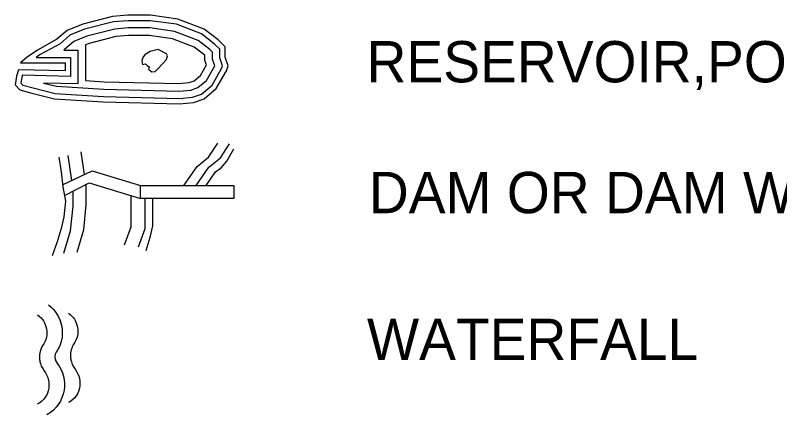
# Model space of a CAD drawing. Extents: x 5197761 to 5514561, y 1890130 to 2080942.
# Drawn here: x 5487538 to 5496796, y 1996107 to 2000941 of the extents above; entities that cross this region are included whole.
import ezdxf

# ---------------------------------------------------------------- set-up
doc = ezdxf.new("R2010")
doc.units = 0
for name, color, linetype in [('Exist Hydrographic Buffer Line', 7, 'Continuous'), ('Exist Hydrographic Island Shore', 7, 'Continuous'), ('Exist Hydrographic Lake Dam', 7, 'Continuous'), ('Exist Hydrographic Lake Shore', 7, 'Continuous'), ('Exist Hydrographic Lake Shore Label', 7, 'Continuous'), ('Exist Hydrographic River Shore', 7, 'Continuous'), ('Exist Hydrographic Waterfall CELL', 7, 'Continuous'), ('Exist Hydrographic Waterfall Label', 7, 'Continuous')]:
    doc.layers.add(name, color=color, linetype=linetype)

msp = doc.modelspace()

# ---------------------------------------------------------------- linework, layer by layer
at = {"layer": 'Exist Hydrographic Buffer Line'}
for points in [[(5487624.3, 2000216.7), (5487617, 2000192.5), (5487606.6, 2000119.7), (5487627.4, 2000096), (5487753.2, 2000062.9), (5488022.7, 1999995.5), (5488605, 1999957.7), (5489526.2, 1999934.9), (5489682.7, 1999949.1), (5489794, 1999988.4), (5489921.6, 2000095.8), (5490035.7, 2000295.5), (5490048.5, 2000329.6), (5490014.4, 2000424.9), (5490014.4, 2000531.7), (5489952.2, 2000593.9), (5489794.7, 2000715.6), (5489489.1, 2000832.1), (5489171.7, 2000876.4), (5488903.3, 2000876.4), (5488727.7, 2000861.7), (5488377.3, 2000772.3), (5488200.2, 2000701.4), (5488080.7, 2000596.9), (5487840.1, 2000464.9), (5487792.7, 2000432.4), (5488207.8, 2000432.4), (5488207.8, 2000200.9)], [(5487880.9, 2000121.7), (5488036.3, 2000082.8), (5488608.9, 2000045.7), (5489523.3, 2000023), (5489663.8, 2000035.8), (5489749.6, 2000066), (5489852.9, 2000153), (5489954.5, 2000330.9), (5489926.4, 2000409.7), (5489926.4, 2000495.3), (5489893.9, 2000527.7), (5489751.2, 2000638), (5489467, 2000746.3), (5489165.6, 2000788.3), (5488907, 2000788.3), (5488742.4, 2000774.6), (5488404.7, 2000688.4), (5488246.9, 2000625.3), (5488131.5, 2000524.3), (5488124.3, 2000520.4), (5488295.9, 2000520.4), (5488295.9, 2000110.5)], [(5489703.2, 2000147.1), (5489781.2, 2000212.8), (5489853.8, 2000339.8), (5489834.5, 2000393.8), (5489834.5, 2000457.2), (5489833.1, 2000458.6), (5489705.8, 2000557), (5489444.1, 2000656.7), (5489159.2, 2000696.5), (5488910.8, 2000696.5), (5488757.6, 2000683.7), (5488433.2, 2000600.9), (5488387.7, 2000582.7), (5488387.7, 2000152.1), (5488613, 2000137.5), (5489520.2, 2000115), (5489644.1, 2000126.2)]]:
    msp.add_lwpolyline(points, close=True, dxfattribs=at)
for points in [[(5489580.5, 1998881.3), (5489739.5, 1999112.5), (5489880.1, 1999223), (5489990.6, 1999393.8)], [(5489728.5, 1998881.3), (5489882.2, 1999104.8), (5490022.8, 1999215.3), (5490133.3, 1999386)], [(5488376.2, 1999014.6), (5488336.4, 1999286.9)], [(5488222.5, 1998941.6), (5488178.1, 1999245.4)], [(5488286.2, 1998075.7), (5488366.5, 1998346.9), (5488396.6, 1998648.2), (5488396.6, 1998893.7)], [(5488127.8, 1998060.1), (5488208.2, 1998331.3), (5488238.3, 1998632.7), (5488238.3, 1998813.4)], [(5488860.7, 1998161.2), (5488941.1, 1998382.2), (5488941.1, 1998573.1), (5488941.1, 1998757.9)], [(5489029.4, 1998140.4), (5489109.7, 1998361.4), (5489109.7, 1998552.3), (5489109.7, 1998723.1)]]:
    msp.add_lwpolyline(points, dxfattribs=at)
at = {"layer": 'Exist Hydrographic Island Shore'}
msp.add_lwpolyline([(5489268, 2000526.1), (5489170.4, 2000505.1), (5489113, 2000468.7), (5489086.2, 2000438.1), (5489069, 2000394.1), (5489080.5, 2000344.3), (5489114.9, 2000355.8), (5489134.1, 2000332.9), (5489162.8, 2000313.7), (5489153.2, 2000288.8), (5489191.5, 2000256.3), (5489231.7, 2000262), (5489264.2, 2000294.6), (5489321.6, 2000352), (5489367.6, 2000405.6), (5489382.9, 2000451.5), (5489367.6, 2000474.5)], close=True, dxfattribs=at)
at = {"layer": 'Exist Hydrographic Lake Dam'}
for points in [[(5488111.5, 1998888.9), (5488470.9, 1999059.6), (5489056, 1998881.3)], [(5488132.6, 1998759.8), (5488432.5, 1998911.9), (5489056, 1998723.1)]]:
    msp.add_lwpolyline(points, dxfattribs=at)
msp.add_lwpolyline([(5489056, 1998881.3), (5490183.5, 1998881.3), (5490183.5, 1998723.1), (5489056, 1998723.1)], close=True, dxfattribs=at)
at = {"layer": 'Exist Hydrographic Lake Shore'}
msp.add_lwpolyline([(5488012.6, 1999931), (5488602.1, 1999892.7), (5489528.3, 1999869.7), (5489696.7, 1999885), (5489826.9, 1999931), (5489972.3, 2000053.4), (5490094.8, 2000267.8), (5490117.8, 2000329), (5490079.5, 2000436.2), (5490079.5, 2000497.4), (5490079.5, 2000558.7), (5489995.3, 2000642.9), (5489826.9, 2000773), (5489505.4, 2000895.5), (5489176.2, 2000941.4), (5488900.6, 2000941.4), (5488716.9, 2000926.1), (5488357.1, 2000834.3), (5488165.7, 2000757.7), (5488043.2, 2000650.5), (5487805.9, 2000520.4), (5487683.5, 2000436.2), (5487599.3, 2000367.3), (5488142.8, 2000367.3), (5488142.8, 2000267.8), (5487576.3, 2000283.1), (5487553.3, 2000206.5), (5487538, 2000099.4), (5487591.6, 2000038.1), (5487737, 1999999.9)], close=True, dxfattribs=at)
at = {"layer": 'Exist Hydrographic River Shore'}
for points in [[(5489850.3, 1998881.3), (5489962.6, 1999044.5), (5490030.4, 1999094.7), (5490100.7, 1999177.6), (5490183.5, 1999325.8)], [(5488064.1, 1999225.3), (5488094.2, 1999044.5), (5488114.3, 1998863.7), (5488144.4, 1998692.9), (5488124.3, 1998502.1), (5488094.2, 1998361.4), (5488044, 1998200.7), (5487983.7, 1998030)], [(5489199.1, 1998723.1), (5489199.1, 1998562.3), (5489199.1, 1998391.6), (5489169, 1998250.9), (5489118.8, 1998090.2)]]:
    msp.add_lwpolyline(points, dxfattribs=at)
at = {"layer": 'Exist Hydrographic Waterfall CELL'}
for points in [[(5487940.1, 1997435), (5487970.9, 1997410), (5487997.3, 1997383), (5488019.5, 1997357.8), (5488042.5, 1997324.7), (5488060.6, 1997292.5), (5488077.7, 1997256.8), (5488090.9, 1997218), (5488101, 1997174.4), (5488106.3, 1997131.2), (5488106.9, 1997086.4), (5488104.4, 1997046.6), (5488092.8, 1996990.7), (5488076, 1996941.9), (5488053.2, 1996895.6), (5488033.4, 1996864.6), (5488027.2, 1996851.7), (5488025.3, 1996847), (5488022.7, 1996838.5), (5488018.3, 1996817.3), (5488017.6, 1996808.8), (5488018.1, 1996795), (5488018.5, 1996793), (5488020.6, 1996783), (5488023.3, 1996770.9), (5488026.7, 1996761.3), (5488036.8, 1996743.3), (5488050.4, 1996721.4), (5488069.6, 1996692.9), (5488089.7, 1996656.3), (5488109, 1996611.9), (5488125, 1996555.8), (5488130.2, 1996521.8), (5488132.7, 1996494.8), (5488133.3, 1996467.4), (5488132.6, 1996443.5), (5488128.5, 1996405.4), (5488117.7, 1996356.5), (5488103.5, 1996315.3), (5488083.8, 1996272), (5488061.1, 1996236), (5488034.7, 1996199.7), (5487999.5, 1996163.2), (5487964.1, 1996134.6), (5487938.4, 1996116.8), (5487920.7, 1996106.5)], [(5487808.3, 1997315.6), (5487832.4, 1997296.1), (5487850.1, 1997277.9), (5487864.1, 1997262.1), (5487878, 1997242.1), (5487890.2, 1997220.5), (5487901.3, 1997197.2), (5487909.2, 1997173.9), (5487915.8, 1997145.5), (5487919.1, 1997118.3), (5487919.5, 1997087.2), (5487918.1, 1997063.7), (5487910.6, 1997027.6), (5487899.9, 1996996.7), (5487885, 1996966.4), (5487864.9, 1996934.9), (5487852.6, 1996909.4), (5487846.5, 1996894.1), (5487840, 1996873.1), (5487832.2, 1996835.6), (5487830.1, 1996808.8), (5487831.3, 1996776.5), (5487833.8, 1996762.1), (5487836.7, 1996748.3), (5487841.7, 1996725.8), (5487852.6, 1996695.9), (5487870.3, 1996664.2), (5487887.2, 1996637), (5487904.1, 1996611.9), (5487917.7, 1996587.2), (5487930.2, 1996558.3), (5487940.8, 1996521), (5487943.9, 1996500.6), (5487945.6, 1996483.1), (5487946, 1996465), (5487945.6, 1996450.8), (5487943, 1996426.9), (5487935.8, 1996394.3), (5487926.7, 1996368), (5487914.3, 1996340.6), (5487899.5, 1996317.3), (5487882.2, 1996293.4), (5487860.7, 1996271.1), (5487836.8, 1996251.8), (5487820.7, 1996240.6), (5487808.3, 1996233.4)], [(5488183.8, 1997335), (5488207.9, 1997315.4), (5488225.6, 1997297.3), (5488239.6, 1997281.4), (5488253.5, 1997261.4), (5488265.7, 1997239.8), (5488276.8, 1997216.5), (5488284.7, 1997193.3), (5488291.3, 1997164.8), (5488294.6, 1997137.6), (5488295, 1997106.5), (5488293.6, 1997083), (5488286.1, 1997047), (5488275.5, 1997016.1), (5488260.5, 1996985.8), (5488240.4, 1996954.3), (5488228.1, 1996928.7), (5488222, 1996913.5), (5488215.5, 1996892.5), (5488207.7, 1996855), (5488205.6, 1996828.2), (5488206.9, 1996795.9), (5488209.3, 1996781.4), (5488212.2, 1996767.6), (5488217.3, 1996745.2), (5488228.1, 1996715.3), (5488245.8, 1996683.6), (5488262.7, 1996656.4), (5488279.6, 1996631.2), (5488293.2, 1996606.5), (5488305.7, 1996577.7), (5488316.4, 1996540.4), (5488319.4, 1996520), (5488321.1, 1996502.5), (5488321.5, 1996484.4), (5488321.1, 1996470.1), (5488318.5, 1996446.2), (5488311.3, 1996413.7), (5488302.2, 1996387.3), (5488289.8, 1996359.9), (5488275, 1996336.6), (5488257.7, 1996312.7), (5488236.2, 1996290.5), (5488212.3, 1996271.1), (5488196.2, 1996260), (5488183.8, 1996252.8)]]:
    msp.add_lwpolyline(points, dxfattribs=at)

# ---------------------------------------------------------------- texts
at = {"layer": 'Exist Hydrographic Lake Shore Label'}
for s, p in [('RESERVOIR,POND,OR LAKE W/ ISLAND', (5491792, 2000129.3)), ('DAM OR DAM WITH LOCK', (5491820.3, 1998545.8))]:
    msp.add_text(s, height=500, dxfattribs=at).set_placement(p)
at = {"layer": 'Exist Hydrographic Waterfall Label'}
msp.add_text('WATERFALL', height=500, dxfattribs=at).set_placement((5491797.9, 1996768.6))

doc.saveas('drawing.dxf')
